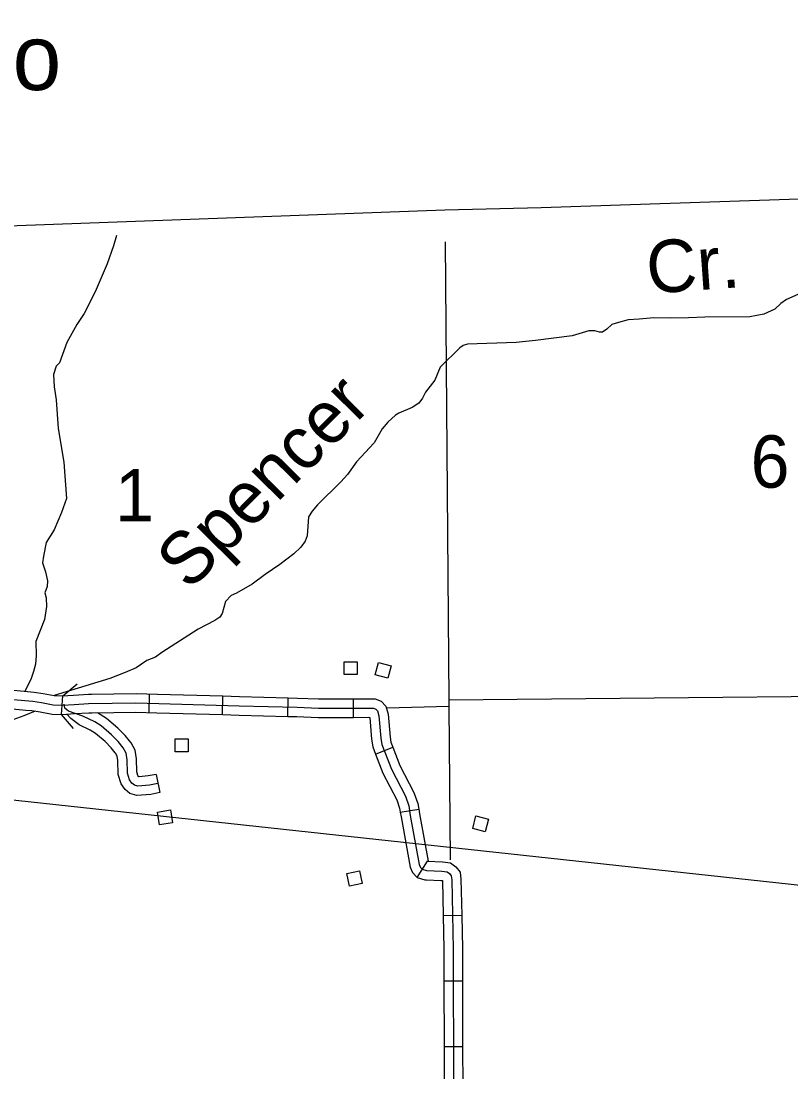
# Model space of a CAD drawing. Extents: x 1369885 to 1370219, y 379980 to 380218.
# Drawn here: x 1370054.99 to 1370079.7, y 380094.55 to 380128.26 of the extents above; entities that cross this region are included whole.
import ezdxf

# ---------------------------------------------------------------- set-up
doc = ezdxf.new("R2010")
doc.units = 0
for name, color, linetype in [('Level 1', 7, 'Continuous'), ('Level 24', 7, 'Continuous'), ('Level 32', 7, 'Continuous'), ('Level 35', 7, 'Continuous'), ('Level 38', 7, 'Continuous'), ('Level 4', 7, 'Continuous'), ('Level 45', 7, 'Continuous'), ('Level 5', 7, 'Continuous'), ('Level 56', 7, 'Continuous'), ('Page Text', 7, 'Continuous')]:
    doc.layers.add(name, color=color, linetype=linetype)

msp = doc.modelspace()

# ---------------------------------------------------------------- linework, layer by layer
at = {"layer": 'Level 1'}
for points in [[(1370068.595, 380122.2), (1370071.687, 380122.275), (1370088.242, 380122.837), (1370088.683, 380122.838), (1370090.411, 380122.931)], [(1370049.023, 380121.49), (1370068.595, 380122.2)]]:
    msp.add_lwpolyline(points, dxfattribs=at)
at = {"layer": 'Level 32'}
for p, q in [((1370056.289, 380106.018), (1370056.339, 380106.613)), ((1370059.104, 380106.078), (1370059.12, 380106.675)), ((1370061.454, 380106.015), (1370061.47, 380106.611)), ((1370063.553, 380105.956), (1370063.57, 380106.553)), ((1370065.662, 380105.924), (1370065.66, 380106.521)), ((1370066.367, 380104.748), (1370066.923, 380104.966)), ((1370067.163, 380102.884), (1370067.753, 380102.976)), ((1370067.702, 380100.789), (1370068.036, 380101.31)), ((1370068.537, 380099.566), (1370069.133, 380099.579)), ((1370068.562, 380097.472), (1370069.158, 380097.473)), ((1370068.567, 380095.371), (1370069.164, 380095.373))]:
    msp.add_line(p, q, dxfattribs=at)
for points in [[(1370053.084, 380106.834), (1370054.754, 380106.793), (1370055.2, 380106.755)], [(1370055.2, 380106.755), (1370055.412, 380106.737), (1370055.706, 380106.694), (1370056.057, 380106.623), (1370056.317, 380106.618), (1370056.681, 380106.64), (1370057.155, 380106.664), (1370057.258, 380106.665)], [(1370057.258, 380106.665), (1370058.684, 380106.686), (1370059.371, 380106.668)], [(1370059.371, 380106.668), (1370061.47, 380106.611)], [(1370061.47, 380106.611), (1370062.007, 380106.597), (1370063.57, 380106.553)], [(1370054.738, 380106.495), (1370055.378, 380106.44), (1370055.655, 380106.4), (1370056.024, 380106.325), (1370056.323, 380106.319), (1370056.698, 380106.342), (1370057.165, 380106.365), (1370058.682, 380106.388), (1370061.998, 380106.299), (1370063.859, 380106.246), (1370064.537, 380106.219), (1370066.139, 380106.224), (1370066.3, 380106.218), (1370066.38, 380106.186), (1370066.433, 380106.129), (1370066.478, 380105.973), (1370066.541, 380105.254), (1370066.568, 380105.053), (1370066.88, 380104.258), (1370067.326, 380103.393), (1370067.433, 380103.089), (1370067.481, 380102.782), (1370067.769, 380101.207), (1370067.808, 380101.108), (1370067.861, 380101.053), (1370068, 380101.013), (1370068.495, 380100.991), (1370068.663, 380100.968), (1370068.742, 380100.913), (1370068.798, 380100.844), (1370068.812, 380100.714), (1370068.857, 380098.493), (1370068.869, 380094.084)], [(1370063.57, 380106.553), (1370063.869, 380106.544), (1370064.542, 380106.518), (1370065.66, 380106.521)], [(1370065.66, 380106.521), (1370066.144, 380106.522), (1370066.362, 380106.515), (1370066.553, 380106.439), (1370066.701, 380106.28), (1370066.773, 380106.027), (1370066.837, 380105.287), (1370066.859, 380105.129), (1370066.923, 380104.966)], [(1370053.07, 380106.237), (1370054.722, 380106.197), (1370055.15, 380106.16)], [(1370055.15, 380106.16), (1370055.344, 380106.144), (1370055.604, 380106.106), (1370055.991, 380106.027), (1370056.33, 380106.021), (1370056.714, 380106.045), (1370057.174, 380106.067), (1370057.267, 380106.069)], [(1370057.267, 380106.069), (1370058.681, 380106.09), (1370059.355, 380106.071)], [(1370059.355, 380106.071), (1370061.454, 380106.015)], [(1370061.454, 380106.015), (1370061.99, 380106), (1370063.553, 380105.956)], [(1370063.553, 380105.956), (1370063.848, 380105.948), (1370064.531, 380105.921), (1370065.662, 380105.924)], [(1370065.662, 380105.924), (1370066.134, 380105.926), (1370066.182, 380105.924), (1370066.183, 380105.918), (1370066.244, 380105.221), (1370066.277, 380104.977), (1370066.367, 380104.748)], [(1370066.923, 380104.966), (1370067.152, 380104.381), (1370067.6, 380103.512), (1370067.723, 380103.163), (1370067.753, 380102.976)], [(1370066.367, 380104.748), (1370066.607, 380104.135), (1370067.051, 380103.275), (1370067.142, 380103.016), (1370067.163, 380102.884)], [(1370067.163, 380102.884), (1370067.187, 380102.732), (1370067.481, 380101.125), (1370067.552, 380100.944), (1370067.702, 380100.789), (1370067.951, 380100.717), (1370068.009, 380100.714)], [(1370067.753, 380102.976), (1370067.775, 380102.832), (1370068.054, 380101.309), (1370068.036, 380101.31)], [(1370068.036, 380101.31), (1370068.522, 380101.288), (1370068.774, 380101.254), (1370068.947, 380101.134), (1370069.086, 380100.962), (1370069.11, 380100.733), (1370069.133, 380099.579)], [(1370068.009, 380100.714), (1370068.468, 380100.694), (1370068.514, 380100.687), (1370068.537, 380099.566)], [(1370068.537, 380099.566), (1370068.559, 380098.49), (1370068.562, 380097.472)], [(1370069.133, 380099.579), (1370069.156, 380098.497), (1370069.158, 380097.473)], [(1370068.562, 380097.472), (1370068.567, 380095.371)], [(1370069.158, 380097.473), (1370069.164, 380095.373)], [(1370068.567, 380095.371), (1370068.571, 380094.083), (1370068.575, 380093.27)], [(1370069.164, 380095.373), (1370069.168, 380094.086), (1370069.172, 380093.273)]]:
    msp.add_lwpolyline(points, dxfattribs=at)
at = {"layer": 'Level 35'}
for points in [[(1370058.06, 380121.377), (1370057.967, 380121.051), (1370057.754, 380120.471), (1370057.372, 380119.57), (1370057.02, 380118.878), (1370056.788, 380118.524), (1370056.46, 380117.952), (1370056.226, 380117.299), (1370056.126, 380117.185), (1370056.039, 380116.919), (1370056.059, 380116.521), (1370056.119, 380116.104), (1370056.186, 380115.189), (1370056.366, 380114.107), (1370056.457, 380112.941), (1370056.292, 380112.494), (1370056.055, 380111.937), (1370055.801, 380111.534), (1370055.711, 380111.094), (1370055.679, 380110.875), (1370055.782, 380110.594), (1370055.849, 380110.304), (1370055.831, 380110.121), (1370055.76, 380109.915), (1370055.8, 380109.759), (1370055.813, 380109.482), (1370055.751, 380109.067), (1370055.468, 380108.359), (1370055.476, 380107.908), (1370055.463, 380107.635), (1370055.4, 380107.4), (1370055.306, 380107.139), (1370055.117, 380106.762)], [(1370080.47, 380119.734), (1370079.553, 380119.323), (1370079.374, 380119.194), (1370079.181, 380119.017), (1370078.832, 380118.859), (1370078.378, 380118.765), (1370076.934, 380118.754), (1370076.407, 380118.741), (1370075.833, 380118.732), (1370075.293, 380118.743), (1370074.827, 380118.692), (1370074.479, 380118.679), (1370074.168, 380118.59), (1370073.949, 380118.523), (1370073.794, 380118.371), (1370073.646, 380118.279), (1370073.555, 380118.28), (1370073.403, 380118.323), (1370073.208, 380118.317), (1370072.681, 380118.158), (1370071.502, 380118.006), (1370070.88, 380117.944), (1370069.316, 380117.892), (1370069.182, 380117.852), (1370069.07, 380117.773), (1370068.445, 380117.156), (1370068.275, 380116.736), (1370067.977, 380116.349), (1370067.879, 380116.162), (1370067.761, 380115.999), (1370067.547, 380115.861), (1370067.119, 380115.681), (1370067.01, 380115.618)], [(1370067.01, 380115.618), (1370066.763, 380115.391), (1370066.586, 380115.174), (1370066.33, 380114.724), (1370065.753, 380114.117), (1370065.471, 380113.717), (1370065.26, 380113.476), (1370064.512, 380112.736), (1370064.335, 380112.539), (1370064.221, 380112.356), (1370064.176, 380111.745), (1370064.11, 380111.571), (1370063.977, 380111.384), (1370063.753, 380111.17), (1370063.298, 380110.829), (1370062.824, 380110.504), (1370062.412, 380110.196), (1370061.904, 380109.911), (1370061.735, 380109.831), (1370061.559, 380109.639), (1370061.449, 380109.254), (1370061.373, 380109.136), (1370061.213, 380109.027), (1370060.681, 380108.752), (1370059.512, 380108.009), (1370059.309, 380107.858), (1370059.028, 380107.744), (1370058.689, 380107.518), (1370058.335, 380107.364), (1370057.846, 380107.173), (1370056.057, 380106.623)], [(1370055.454, 380106.128), (1370055.082, 380105.97), (1370054.735, 380105.847)]]:
    msp.add_lwpolyline(points, dxfattribs=at)
at = {"layer": 'Level 38'}
for points in [[(1370056.339, 380106.613), (1370056.795, 380106.998)], [(1370056.674, 380105.562), (1370056.289, 380106.018)]]:
    msp.add_lwpolyline(points, dxfattribs=at)
at = {"layer": 'Level 4'}
msp.add_lwpolyline([(1370068.603, 380121.171), (1370068.72, 380106.473), (1370068.721, 380106.276), (1370068.763, 380101.36)], dxfattribs=at)
at = {"layer": 'Level 45'}
msp.add_line((1370059.328, 380104.096), (1370059.447, 380103.511), dxfattribs=at)
for points in [[(1370059.388, 380103.803), (1370059.119, 380103.749), (1370058.747, 380103.717), (1370058.634, 380103.754), (1370058.553, 380103.819), (1370058.474, 380103.924), (1370058.412, 380104.134), (1370058.402, 380104.564), (1370058.368, 380104.772), (1370058.275, 380104.945), (1370058.108, 380105.147), (1370057.901, 380105.366), (1370057.562, 380105.65), (1370057.362, 380105.776), (1370056.973, 380105.966), (1370056.518, 380106.127), (1370056.46, 380106.162), (1370056.403, 380106.219), (1370056.38, 380106.346)], [(1370058.018, 380104.788), (1370057.885, 380104.949), (1370057.696, 380105.148), (1370057.386, 380105.409), (1370057.217, 380105.515), (1370056.858, 380105.69), (1370056.594, 380105.886), (1370056.462, 380106.029)], [(1370058.478, 380105.168), (1370058.332, 380105.345), (1370058.106, 380105.583), (1370057.738, 380105.892), (1370057.452, 380106.071)], [(1370059.328, 380104.096), (1370059.077, 380104.044), (1370058.782, 380104.02), (1370058.778, 380104.021), (1370058.769, 380104.028), (1370058.745, 380104.06), (1370058.71, 380104.18), (1370058.7, 380104.592), (1370058.654, 380104.869), (1370058.525, 380105.112), (1370058.478, 380105.168)], [(1370059.447, 380103.511), (1370059.161, 380103.453), (1370058.712, 380103.415), (1370058.49, 380103.487), (1370058.337, 380103.61), (1370058.203, 380103.788), (1370058.115, 380104.087), (1370058.105, 380104.536), (1370058.081, 380104.675), (1370058.026, 380104.778), (1370058.018, 380104.788)]]:
    msp.add_lwpolyline(points, dxfattribs=at)
at = {"layer": 'Level 5'}
for points in [[(1370088.494, 380106.671), (1370068.72, 380106.473)], [(1370068.721, 380106.276), (1370066.735, 380106.218)]]:
    msp.add_lwpolyline(points, dxfattribs=at)
at = {"layer": 'Level 56'}
for points in [[(1370065.365, 380107.295), (1370065.365, 380107.709), (1370065.781, 380107.709), (1370065.781, 380107.295)], [(1370066.361, 380107.288), (1370066.466, 380107.688), (1370066.868, 380107.582), (1370066.762, 380107.182)], [(1370059.938, 380104.822), (1370059.938, 380105.236), (1370060.353, 380105.236), (1370060.353, 380104.822)], [(1370059.443, 380102.48), (1370059.378, 380102.889), (1370059.789, 380102.954), (1370059.853, 380102.545)], [(1370069.486, 380102.364), (1370069.592, 380102.764), (1370069.994, 380102.658), (1370069.888, 380102.257)], [(1370065.533, 380100.508), (1370065.449, 380100.914), (1370065.856, 380100.998), (1370065.94, 380100.593)]]:
    msp.add_lwpolyline(points, close=True, dxfattribs=at)
at = {"layer": 'Page Text'}
msp.add_lwpolyline([(1370047.12, 380104.1), (1370131.535, 380094.962)], dxfattribs=at)

# ---------------------------------------------------------------- texts
at = {"layer": 'Level 24'}
msp.add_text('Doniphan, Mo', height=2.10029, dxfattribs=at).set_placement((1370038.8, 380126.045))
at = {"layer": 'Level 35'}
for s, rotation, p in [('Cr.', 4.0884, (1370075.116, 380119.509)), ('Spencer', 45.2491, (1370060.389, 380109.95))]:
    msp.add_text(s, height=1.6802, rotation=rotation, dxfattribs=at).set_placement(p)
at = {"layer": 'Level 5'}
for s, p in [('6', (1370078.402, 380113.291)), ('1', (1370058.011, 380112.206))]:
    msp.add_text(s, height=1.68, dxfattribs=at).set_placement(p)

doc.saveas('drawing.dxf')
